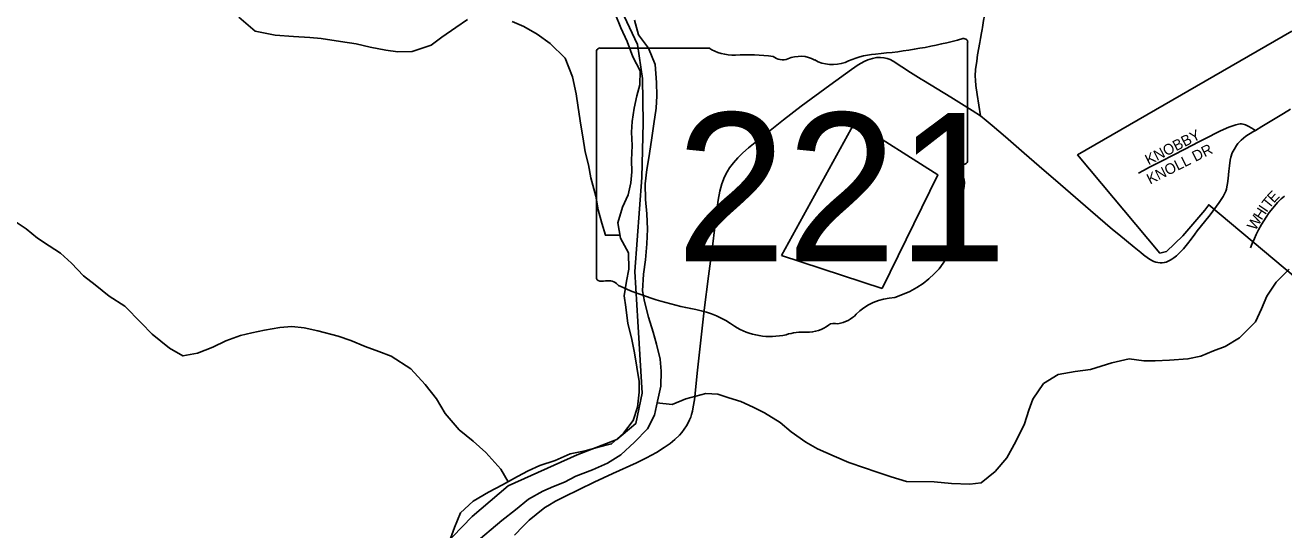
# Model space of a CAD drawing. Extents: x 1451455 to 1749751, y 218250 to 574981.
# Drawn here: x 1559745 to 1565644, y 315756 to 318123 of the extents above; entities that cross this region are included whole.
import ezdxf

# ---------------------------------------------------------------- set-up
doc = ezdxf.new("R2010")
doc.units = 0
for name, color, linetype in [('GM_X_City_Street', 7, 'Continuous'), ('GM_X_City_Street_Text', 7, 'Continuous'), ('GM_X_Corporation', 7, 'Continuous'), ('GM_X_Major_River', 7, 'Continuous'), ('GM_X_Minor_Lake', 7, 'Continuous'), ('GM_X_Minor_River', 7, 'Continuous'), ('GM_X_State_Location', 7, 'Continuous'), ('GM_X_State_Route', 7, 'Continuous'), ('GM_X_State_Shield', 7, 'Continuous'), ('GM_X_Township', 7, 'Continuous'), ('GM_X_Township_Road', 7, 'Continuous')]:
    doc.layers.add(name, color=color, linetype=linetype)

msp = doc.modelspace()

# ---------------------------------------------------------------- linework, layer by layer
at = {"layer": 'GM_X_City_Street'}
for points in [[(1564962.2, 317429.3), (1564986.6, 317441.9), (1565014.1, 317456.1), (1565071.4, 317485.7), (1565125, 317512.8), (1565179.9, 317541.3), (1565246.4, 317575.5), (1565295.1, 317600.6), (1565322.5, 317614.4), (1565346.6, 317626.5), (1565385.8, 317643.9), (1565405.4, 317651.3), (1565419.1, 317655.4), (1565431.3, 317658.3), (1565439.4, 317659.5), (1565446.1, 317659.4), (1565452.3, 317658.9), (1565458.3, 317657.6), (1565464.7, 317655.4), (1565476.4, 317648.9), (1565493.5, 317639.4), (1565503.5, 317633.9), (1565511.5, 317629.4)], [(1565488.2, 317078.1), (1565496.4, 317098.6), (1565506.2, 317122.1), (1565515, 317141.6), (1565525.2, 317162.4), (1565538.9, 317188.1), (1565560.6, 317221.7), (1565575.7, 317243.9), (1565592, 317264.8), (1565614.4, 317291), (1565631.5, 317308.5), (1565646.5, 317321.2)]]:
    msp.add_lwpolyline(points, dxfattribs=at)
at = {"layer": 'GM_X_Corporation'}
msp.add_lwpolyline([(1565805.5, 316849.8), (1565292.3, 317280.5), (1565274.3, 317254.7), (1565171.1, 317135.4), (1565094.3, 317062), (1565063.3, 317054.1), (1564677.6, 317513.9), (1565682.3, 318094.2)], dxfattribs=at)
at = {"layer": 'GM_X_Major_River'}
for points in [[(1562509.7, 318175), (1562536.7, 318110.5), (1562565.6, 318046), (1562592.5, 317973.5), (1562627.4, 317908.9), (1562626.4, 317842.9), (1562611.6, 317791), (1562598.8, 317733.2), (1562589.9, 317671.2), (1562587.1, 317621.2), (1562590.2, 317559.1), (1562587.1, 317489.1), (1562588.3, 317435), (1562583.5, 317383), (1562570.7, 317327.1), (1562543.8, 317269.5), (1562522.8, 317195.7), (1562535.6, 317123.5), (1562572.5, 317054.8), (1562573.4, 316978.7), (1562562.5, 316922.8), (1562551.5, 316852.9), (1562560.7, 316800.7), (1562569.5, 316724.5), (1562586.4, 316656.2), (1562601.3, 316585.9), (1562612.3, 316519.6), (1562623.2, 316451.4), (1562622.5, 316401.3), (1562615.4, 316331.4), (1562594.5, 316269.6), (1562549.7, 316210.2), (1562493.1, 316159.1), (1562424.9, 316142.1), (1562368.8, 316126.9), (1562298.8, 316112), (1562228.4, 316081), (1562156.2, 316058.1), (1562102, 316032.9), (1562051.7, 316005.7), (1561981.2, 315966.7), (1561916.9, 315933.6), (1561844.4, 315890.7), (1561785.6, 315835.6), (1561756.7, 315767.9), (1561737.9, 315716.2)], [(1561849.3, 315690.4), (1561978.7, 315800.6), (1562043.3, 315849.6), (1562104, 315900.8), (1562170.4, 315937.8), (1562220.6, 315959), (1562272.8, 315980.2), (1562325.1, 316007.5), (1562403.4, 316038.3), (1562473.7, 316069.2), (1562536.2, 316108.3), (1562601, 316167.4), (1562661.8, 316230.5), (1562694.7, 316294.1), (1562707.7, 316360), (1562724.7, 316429.8), (1562725.7, 316499.9), (1562720.6, 316556), (1562703.7, 316626.3), (1562688.6, 316682.6), (1562665.7, 316753.1), (1562646.9, 316827.4), (1562637.7, 316877.6), (1562642.9, 316955.6), (1562651.8, 317021.6), (1562659, 317097.5), (1562662, 317165.6), (1562659.1, 317237.7), (1562652.2, 317305.9), (1562651.3, 317378), (1562658.3, 317445.9), (1562667.1, 317499.9), (1562680.3, 317583.8), (1562691.5, 317659.7), (1562702.6, 317733.6), (1562705.5, 317791.6), (1562704.4, 317853.7), (1562697.7, 317937.9), (1562666.9, 318014.4), (1562620, 318077.2), (1562601.1, 318145.6)]]:
    msp.add_lwpolyline(points, dxfattribs=at)
at = {"layer": 'GM_X_Minor_Lake'}
for points in [[(1563761.1, 316888.6), (1564021.7, 317421.3), (1563634, 317667.8), (1563289.9, 317042.2)], [(1563289.9, 317042.2), (1563761.1, 316888.6)]]:
    msp.add_lwpolyline(points, dxfattribs=at)
at = {"layer": 'GM_X_Minor_River'}
for points in [[(1561817.3, 318148.9), (1561762.7, 318111.7), (1561698, 318066.7), (1561647.5, 318029.4), (1561559, 317998.8), (1561491.1, 317997.8), (1561435.2, 318004.7), (1561361.5, 318019.9), (1561295.8, 318035), (1561222, 318046.1), (1561132.3, 318059.6), (1561078.4, 318064.4), (1561002.6, 318069.6), (1560916.7, 318075), (1560823.1, 318094.5), (1560746.3, 318159.8)], [(1562533.1, 317137.6), (1562464.1, 317137.3), (1562447.1, 317193.6), (1562430.1, 317256), (1562419.2, 317320.3), (1562396.6, 317406.7), (1562385.6, 317467), (1562368.7, 317529.4), (1562357.8, 317599.6), (1562348.7, 317653.8), (1562336.1, 317736.2), (1562327.2, 317800.4), (1562310.5, 317880.8), (1562276, 317967.4), (1562205.2, 318036.6), (1562143.9, 318079.7), (1562082.6, 318116.7), (1562027, 318139.6)], [(1562008, 315981.5), (1561974.4, 316041.4), (1561903.7, 316118.6), (1561844.6, 316171.6), (1561779.5, 316224.8), (1561712.9, 316301.9), (1561672, 316370.6), (1561619.2, 316437.6), (1561552.4, 316510.7), (1561459.5, 316570.3), (1561401.9, 316593.2), (1561338.3, 316616.2), (1561270.8, 316643.4), (1561211.2, 316664.3), (1561115.7, 316689.9), (1561051.9, 316702.9), (1560994.1, 316709.8), (1560938.1, 316704.7), (1560865.9, 316691.8), (1560807.8, 316680.7), (1560753.6, 316667.6), (1560685.2, 316642.6), (1560624.8, 316613.5), (1560552.3, 316584.6), (1560484.2, 316571.7), (1560420.8, 316608.7), (1560340, 316674.1), (1560288.9, 316727), (1560212.2, 316804.3), (1560139.1, 316851.5), (1560072, 316904.7), (1560018.7, 316947.6), (1559961.7, 317006.5), (1559910.5, 317053.4), (1559857.2, 317088.3), (1559801.8, 317123.2), (1559748.6, 317168.2), (1559679.4, 317215.3)], [(1562706, 316351.6), (1562776.8, 316343.3), (1562841.2, 316370.3), (1562935.5, 316394.8), (1562991.4, 316392), (1563043.1, 316375.1), (1563098.8, 316358.2), (1563156.3, 316331.3), (1563209.8, 316304.4), (1563283, 316259.2), (1563334.3, 316216.3), (1563403.4, 316167.2), (1563458.8, 316136.3), (1563536.2, 316101), (1563605.7, 316071.9), (1563679.2, 316046.7), (1563732.8, 316027.8), (1563804.4, 316004.7), (1563876, 315983.5), (1564005.9, 315981.5), (1564085.7, 315974.3), (1564171.6, 315970.9), (1564225.6, 315976.1), (1564290.5, 316029.1), (1564345.5, 316094.4), (1564388.7, 316169.8), (1564428.1, 316253.3), (1564449.1, 316317.1), (1564467.9, 316368.9), (1564517.1, 316442.2), (1564585.8, 316485.2), (1564665.9, 316498), (1564738.1, 316508.8), (1564838.5, 316539.3), (1564918.7, 316558.1), (1564988.5, 316549), (1565040.5, 316548.2), (1565108.5, 316551.1), (1565194.5, 316557.8), (1565254.7, 316570.9), (1565315.1, 316596), (1565369.3, 316615.2), (1565436, 316656.2), (1565511.2, 316731.1), (1565540.2, 316792.8), (1565565.1, 316852.5), (1565608.2, 316917.9), (1565669.1, 316979)]]:
    msp.add_lwpolyline(points, dxfattribs=at)
at = {"layer": 'GM_X_State_Route'}
for points in [[(1562037.8, 315731.8), (1562078.9, 315774.1), (1562107, 315801.3), (1562139, 315829), (1562180.1, 315860.9), (1562193.8, 315869.3), (1562230.4, 315890.2), (1562270.3, 315911.6), (1562410.9, 315979.1), (1562499.6, 316021), (1562610.4, 316070.5), (1562657.4, 316094), (1562703.5, 316119.5), (1562740, 316142), (1562767.1, 316161), (1562790.3, 316179.7), (1562811.9, 316200.5), (1562822.7, 316213.2), (1562834, 316228.2), (1562844.5, 316244), (1562853.5, 316260.5), (1562858.9, 316272.1), (1562864.2, 316285.3), (1562867.4, 316297.1), (1562872, 316313.4), (1562875.9, 316333.1), (1562882, 316365.5), (1562896.2, 316505.4), (1562927.1, 316785.8), (1562947.2, 316945.2), (1562967.6, 317098), (1562982.9, 317228.1), (1562992.7, 317302.7), (1563000.6, 317344.2), (1563009.8, 317378.6), (1563022.3, 317411.7), (1563034.5, 317434.4), (1563046.5, 317453.6), (1563064.1, 317476.8), (1563085.4, 317501.1), (1563108.6, 317523.9), (1563135.6, 317547.6), (1563299.5, 317678.1), (1563382.3, 317742.1), (1563516.9, 317841.1), (1563617, 317915.2), (1563649.4, 317937.1), (1563677.5, 317952.8), (1563695, 317960.4), (1563716.2, 317967), (1563734.9, 317970.3), (1563753.9, 317971.2), (1563769.5, 317969.9), (1563784.8, 317966.6), (1563799.5, 317961.4), (1563813.3, 317953.8), (1563894.1, 317900.8), (1563944.1, 317870.2), (1563955.3, 317863.3), (1564083.5, 317784.4), (1564182.7, 317722.4), (1564221.8, 317696.8), (1564248.2, 317676), (1564276.3, 317652.2), (1564339, 317599.1), (1564426.7, 317521.9), (1564497.3, 317461.3), (1564597.4, 317375.4), (1564737.4, 317254.1), (1564841.2, 317164.8), (1564870.4, 317140.7), (1564942.9, 317081.2), (1564973.9, 317056), (1564986.8, 317045.6), (1565010.4, 317027.8), (1565024.8, 317019.2), (1565034.9, 317014.2), (1565044.3, 317010.9), (1565053.8, 317009.1), (1565064.3, 317008.4), (1565073.7, 317008.4), (1565083.5, 317009.5), (1565092.1, 317011.7), (1565102.3, 317015.6), (1565111.9, 317021), (1565119.6, 317026.1), (1565128.4, 317031.8), (1565140.9, 317041.2), (1565150.7, 317049.8), (1565162, 317060.9)], [(1565238.6, 317159), (1565251.6, 317175.5), (1565299, 317233.4), (1565341, 317291.7), (1565359.5, 317319.8), (1565367.7, 317334.2), (1565372.1, 317344.9), (1565375.1, 317354.2), (1565377.4, 317364), (1565379.9, 317380.9), (1565383.3, 317403.5), (1565386.4, 317437.7), (1565389.1, 317462.6), (1565392.6, 317489.9), (1565395.2, 317503.6), (1565402.4, 317524.5), (1565410.6, 317539.6), (1565422, 317558), (1565428.9, 317567.6), (1565436.8, 317575.9), (1565444.8, 317583.1), (1565455.8, 317592.9), (1565466.6, 317601.4), (1565498.9, 317622.5), (1565511.5, 317629.4), (1565541, 317646.9), (1565618.8, 317693.6), (1565643.1, 317708.6), (1565674.9, 317728.1)], [(1565162, 317060.9), (1565173.5, 317073.4), (1565192.7, 317097.1), (1565209.8, 317119.1), (1565226.8, 317142), (1565238.6, 317159)]]:
    msp.add_lwpolyline(points, dxfattribs=at)
at = {"layer": 'GM_X_State_Shield'}
for p, q in [((1564162.2, 317489), (1564162.2, 318041.7)), ((1562422, 317997.3), (1562422, 316940.7)), ((1562948.7, 318015.5), (1562439.1, 318015.5)), ((1564162, 317489.1), (1564162.2, 317489))]:
    msp.add_line(p, q, dxfattribs=at)
for centre, major_axis, start_param, end_param in [((1563542.3, 319456.1), (1845.5, 0), 4.814394, 5.042369), ((1564142.9, 318044), (19.4, 0), 6.141152, 7.989035), ((1562441.9, 317999.6), (20.2, 0), 1.712693, 3.28349), ((1563070.1, 318138.2), (195.5, 0), 4.042523, 4.731795), ((1563134.9, 317422.3), (702, 0), 1.404758, 1.657858), ((1563377.1, 317882.9), (117.3, 0), 0.950623, 2.079405), ((1563777.7, 317692.8), (371.3, 0), 1.699011, 2.107814), ((1563294.3, 318005.1), (56.4, 0), 3.836095, 5.185415), ((1563528.5, 318050.5), (141.1, 0), 4.081561, 5.145723), ((1564157.7, 317448.4), (30, 0), 1.883978, 3.671073), ((1564141.5, 317486.8), (20.7, 0), 5.05454, 6.418171), ((1563966.9, 317378.5), (180, 0), 5.934695, 6.695948), ((1564231.6, 317257.7), (130.9, 0), 2.387724, 3.262537), ((1563645.7, 317187.3), (461.6, 0), 5.101752, 6.440018), ((1562442.1, 316938.4), (20.3, 0), 3.00124, 4.508301), ((1562445.2, 317046.5), (155.2, 0), 4.665946, 4.897461), ((1562476.9, 316879.7), (56, 0), 0.519207, 1.627899), ((1563183.5, 317829.1), (1332.7, 0), 4.195997, 4.488961), ((1563840.3, 316644.1), (252.8, 0), 1.647645, 2.488434), ((1562786.2, 316466), (417, 0), 0.823519, 1.323587), ((1563520, 316838.3), (149.1, 0), 4.937069, 5.64225), ((1563237.2, 316874.5), (264.6, 0), 4.026481, 4.996735), ((1563390.1, 316509.2), (217.4, 0), 1.495662, 1.94098), ((1563409.4, 316795.4), (141, 0), 4.691044, 5.507374), ((1563536.9, 316693), (39.7, 0), 1.147584, 2.315152)]:
    msp.add_ellipse(centre, major_axis=major_axis, ratio=0.8, start_param=start_param, end_param=end_param, dxfattribs=at)
at = {"layer": 'GM_X_Township'}
msp.add_lwpolyline([(1562450.8, 318381.4), (1562615, 318031.7), (1562637.6, 317873.1), (1562641.9, 317665), (1562634.8, 317408.7), (1562602.3, 316967), (1562616.2, 316732.7), (1562636.3, 316396.4), (1562606.6, 316254.8), (1562517.4, 316179.8), (1562332, 316107.6), (1562007.8, 315963.2), (1561839.4, 315818.9), (1561655.4, 315627.8)], dxfattribs=at)
msp.add_lwpolyline([(1562450.8, 318381.4), (1562615, 318031.7), (1562637.6, 317873.1), (1562641.9, 317665), (1562634.8, 317408.7), (1562602.3, 316967), (1562616.2, 316732.7), (1562636.3, 316396.4), (1562606.6, 316254.8), (1562517.4, 316179.8), (1562332, 316107.6), (1562007.8, 315963.2), (1561839.4, 315818.9), (1561655.4, 315627.8)], dxfattribs=at)
at = {"layer": 'GM_X_Township_Road'}
msp.add_lwpolyline([(1564221.8, 317696.8), (1564206.5, 317797.6), (1564200.2, 317839.8), (1564198.3, 317862.6), (1564197.8, 317885.5), (1564199.6, 317914.9), (1564204.5, 317953.9), (1564209, 317983), (1564218.9, 318041.3), (1564222.4, 318060.6), (1564227.2, 318086.4), (1564229.9, 318102.6), (1564231.7, 318112.2), (1564237.2, 318144.3), (1564241.2, 318166.7), (1564247.4, 318198.5), (1564255.5, 318236.4), (1564264.9, 318280.7), (1564268.3, 318296.4), (1564274.9, 318331.6), (1564281.2, 318366.1)], dxfattribs=at)

# ---------------------------------------------------------------- texts
at = {"layer": 'GM_X_City_Street_Text'}
for s, rotation, p in [('KNOBBY', 26.99494, (1565009.8, 317465)), ('KNOLL DR', 26.56708, (1565016.8, 317374.6)), ('E', 46.8937, (1565597.1, 317285.6)), ('I', 55.67946, (1565563.8, 317241.7)), ('T', 50.97108, (1565575.6, 317258.9)), ('W', 58.8171, (1565511, 317156.2)), ('H', 57.54053, (1565540.4, 317204.9))]:
    msp.add_text(s, height=50, rotation=rotation, dxfattribs=at).set_placement(p)
at = {"layer": 'GM_X_State_Location'}
for s in ['s', 'r']:
    msp.add_text(s, height=1, dxfattribs=at).set_placement((1563272.5, 317398.8))
msp.add_text('221', height=1, rotation=0.00001, dxfattribs=at).set_placement((1562919.5, 317326))
at = {"layer": 'GM_X_State_Shield'}
msp.add_text('221', height=696.1, dxfattribs=at).set_placement((1562794.5, 317015.2))

doc.saveas('drawing.dxf')
